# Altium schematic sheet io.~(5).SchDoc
size Letter
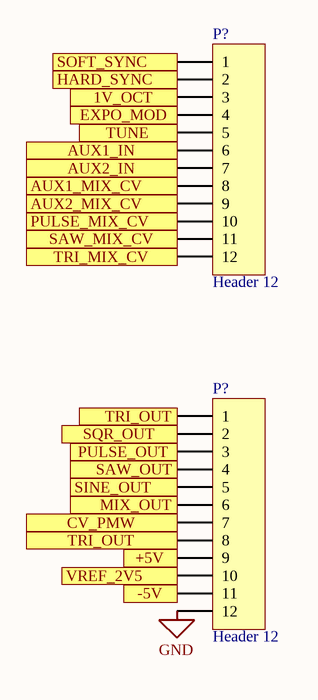
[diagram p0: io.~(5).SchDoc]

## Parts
(Parts that share a designator on the sheet are numbered #1, #2 ... from top to bottom, then left to right.)
P?#1  Header 12  [HDR1X12]
P?#2  Header 12  [HDR1X12]

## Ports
1V_OCT, +5V, -5V, AUX1_IN, AUX1_MIX_CV, AUX2_IN, AUX2_MIX_CV, CV_PMW, EXPO_MOD, HARD_SYNC, MIX_OUT, PULSE_MIX_CV, PULSE_OUT, SAW_MIX_CV, SAW_OUT, SINE_OUT, SOFT_SYNC, SQR_OUT, TRI_MIX_CV, TRI_OUT, TUNE, VREF_2V5

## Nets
GND: P?#2.12
1V_OCT: P?#1.3 ; port 1V_OCT
+5V: P?#2.9 ; port +5V
-5V: P?#2.11 ; port -5V
AUX1_IN: P?#1.6 ; port AUX1_IN
AUX1_MIX_CV: P?#1.8 ; port AUX1_MIX_CV
AUX2_IN: P?#1.7 ; port AUX2_IN
AUX2_MIX_CV: P?#1.9 ; port AUX2_MIX_CV
CV_PMW: P?#2.7 ; port CV_PMW
EXPO_MOD: P?#1.4 ; port EXPO_MOD
HARD_SYNC: P?#1.2 ; port HARD_SYNC
MIX_OUT: P?#2.6 ; port MIX_OUT
PULSE_MIX_CV: P?#1.10 ; port PULSE_MIX_CV
PULSE_OUT: P?#2.3 ; port PULSE_OUT
SAW_MIX_CV: P?#1.11 ; port SAW_MIX_CV
SAW_OUT: P?#2.4 ; port SAW_OUT
SINE_OUT: P?#2.5 ; port SINE_OUT
SOFT_SYNC: P?#1.1 ; port SOFT_SYNC
SQR_OUT: P?#2.2 ; port SQR_OUT
TRI_MIX_CV: P?#1.12 ; port TRI_MIX_CV
TRI_OUT: P?#2.1 P?#2.8 ; port TRI_OUT
TUNE: P?#1.5 ; port TUNE
VREF_2V5: P?#2.10 ; port VREF_2V5

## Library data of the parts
P?#1 P?#2 = Header 12: Header, 12-Pin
